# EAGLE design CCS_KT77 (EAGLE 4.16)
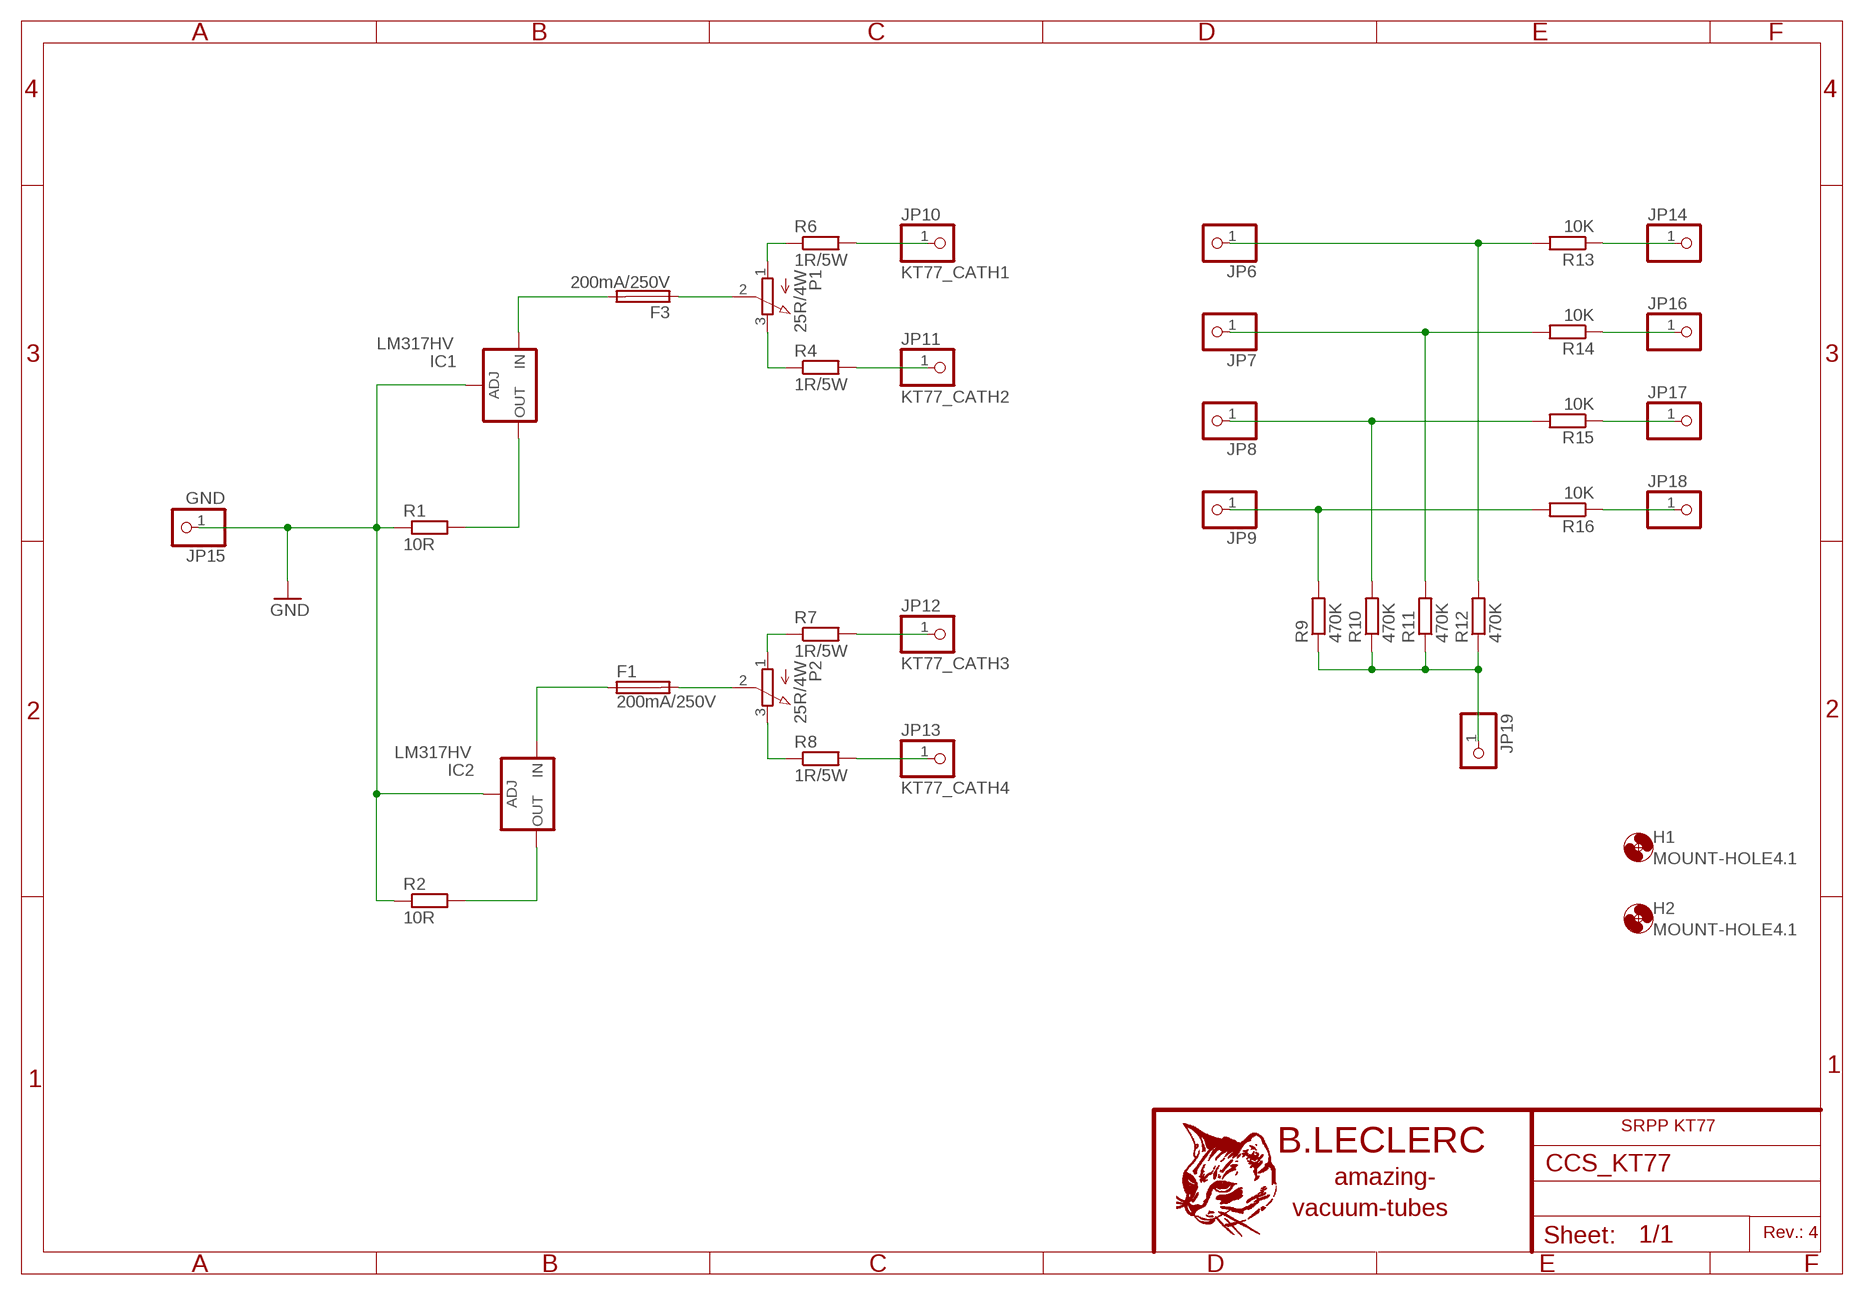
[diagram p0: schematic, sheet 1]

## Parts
F1  200mA/250V  FUSESH22  [SH22]
F3  200mA/250V  FUSESH22  [SH22]
H1  MOUNT-HOLE4.1  [4,1]
H2  MOUNT-HOLE4.1  [4,1]
IC1  LM317HV  LM317MBT  [TO220L1]
IC2  LM317HV  LM317MBT  [TO220L1]
JP6  PINHD-1X1  [1X01]
JP7  PINHD-1X1  [1X01]
JP8  PINHD-1X1  [1X01]
JP9  PINHD-1X1  [1X01]
JP10  KT77_CATH1  PINHD-1X1  [1X01]
JP11  KT77_CATH2  PINHD-1X1  [1X01]
JP12  KT77_CATH3  PINHD-1X1  [1X01]
JP13  KT77_CATH4  PINHD-1X1  [1X01]
JP14  PINHD-1X1  [1X01]
JP15  GND  PINHD-1X1  [1X01]
JP16  PINHD-1X1  [1X01]
JP17  PINHD-1X1  [1X01]
JP18  PINHD-1X1  [1X01]
JP19  PINHD-1X1  [1X01]
P1  25R/4W  STD-EU  [STD-EU]
P2  25R/4W  STD-EU  [STD-EU]
R1  10R  R-EU_0411/15  [0411/15]
R2  10R  R-EU_0411/15  [0411/15]
R4  1R/5W  R-EU_0617/17  [0617/17]
R6  1R/5W  R-EU_0617/17  [0617/17]
R7  1R/5W  R-EU_0617/17  [0617/17]
R8  1R/5W  R-EU_0617/17  [0617/17]
R9  470K  R-EU_0414/15  [0414/15]
R10  470K  R-EU_0414/15  [0414/15]
R11  470K  R-EU_0414/15  [0414/15]
R12  470K  R-EU_0414/15  [0414/15]
R13  10K  R-EU_0414/15  [0414/15]
R14  10K  R-EU_0414/15  [0414/15]
R15  10K  R-EU_0414/15  [0414/15]
R16  10K  R-EU_0414/15  [0414/15]

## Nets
GND: IC1.1(ADJ) IC2.1(ADJ) JP15.1 R1.1 R2.1
N$1: F3.1 P1.2(S)
N$2: IC2.2(OUT) R2.2
N$3: F1.2 P2.2(S)
N$4: F3.2 IC1.3(IN)
N$5: JP10.1 R6.2
N$6: JP12.1 R7.2
N$13: JP11.1 R4.2
N$14: JP13.1 R8.2
N$18: P2.1(A) R7.1
N$20: P2.3(E) R8.1
N$24: P1.3(E) R4.1
N$26: P1.1(A) R6.1
N$27: IC1.2(OUT) R1.2
N$28: F1.1 IC2.3(IN)
N$36: JP6.1 R12.2 R13.2
N$37: JP7.1 R11.2 R14.2
N$38: JP8.1 R10.2 R15.2
N$39: JP9.1 R9.2 R16.2
N$40: JP14.1 R13.1
N$41: JP16.1 R14.1
N$42: JP17.1 R15.1
N$43: JP18.1 R16.1
N$44: JP19.1 R9.1 R10.1 R11.1 R12.1

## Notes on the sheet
- SRPP KT77
- Rev.: 4

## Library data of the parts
F1 F3 = fuse:FUSE: Fuse
H1 H2 = holes:MOUNT-HOLE: MOUNTING HOLE with drill center marker
IC1 IC2 = v-reg:LM317?*: 500 mA Adjustable Output Positive Voltage Regulator Source: http://www.onsemi.co.jp .. LM317M-D.PDF
JP6-JP19 = pinhead:PINHD-1X1: PIN HEADER
P1 P2 = pot:STD-EU
R1 R2 R4 R6-R16 = rcl:R-EU_: RESISTOR, European symbol

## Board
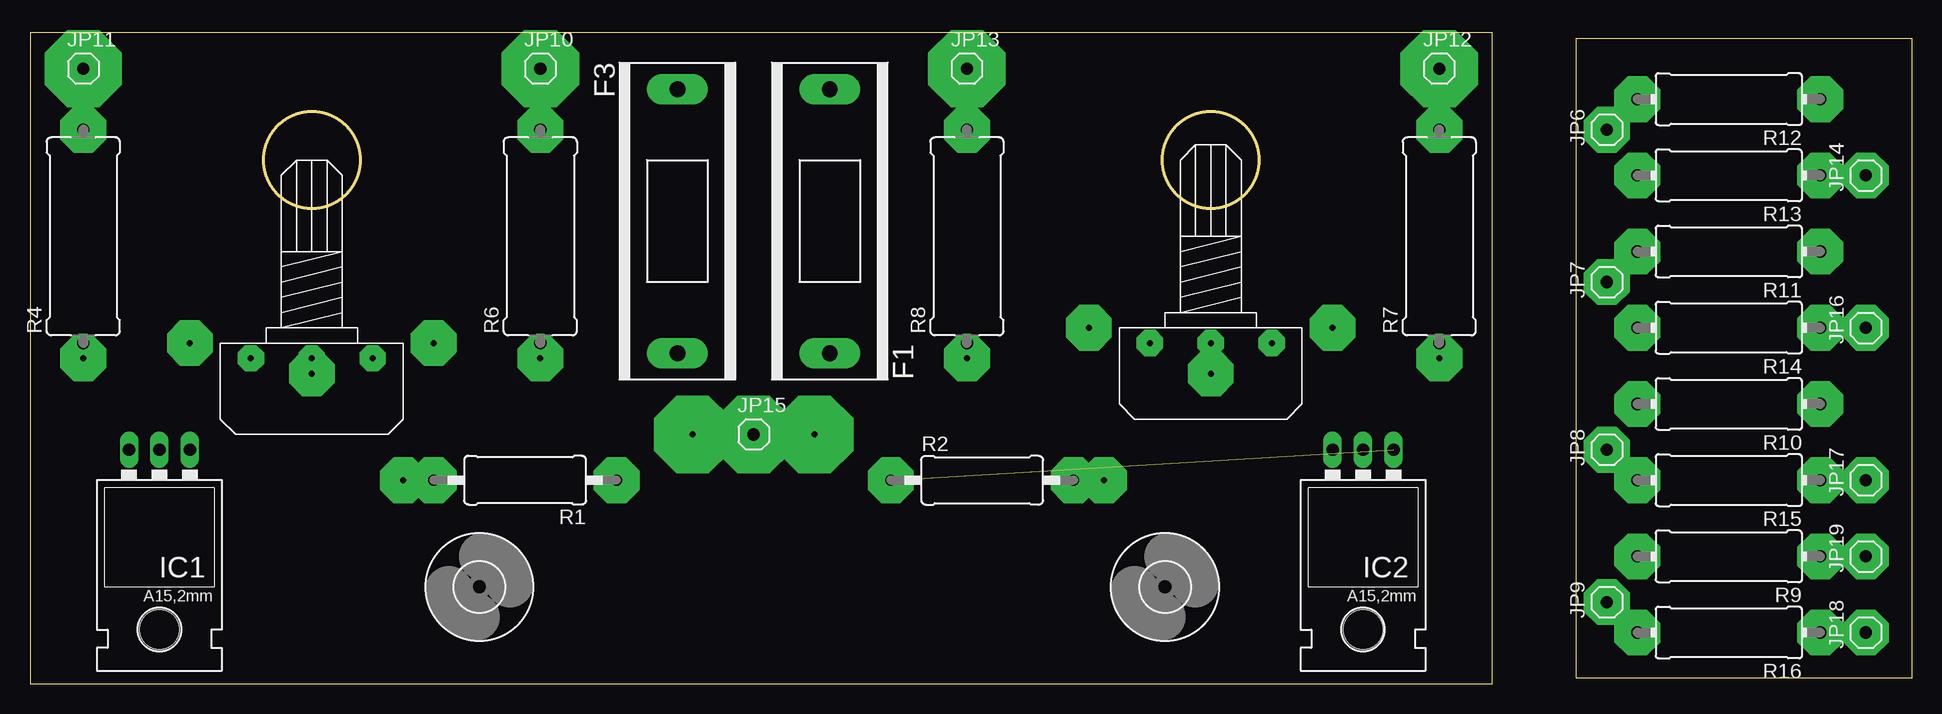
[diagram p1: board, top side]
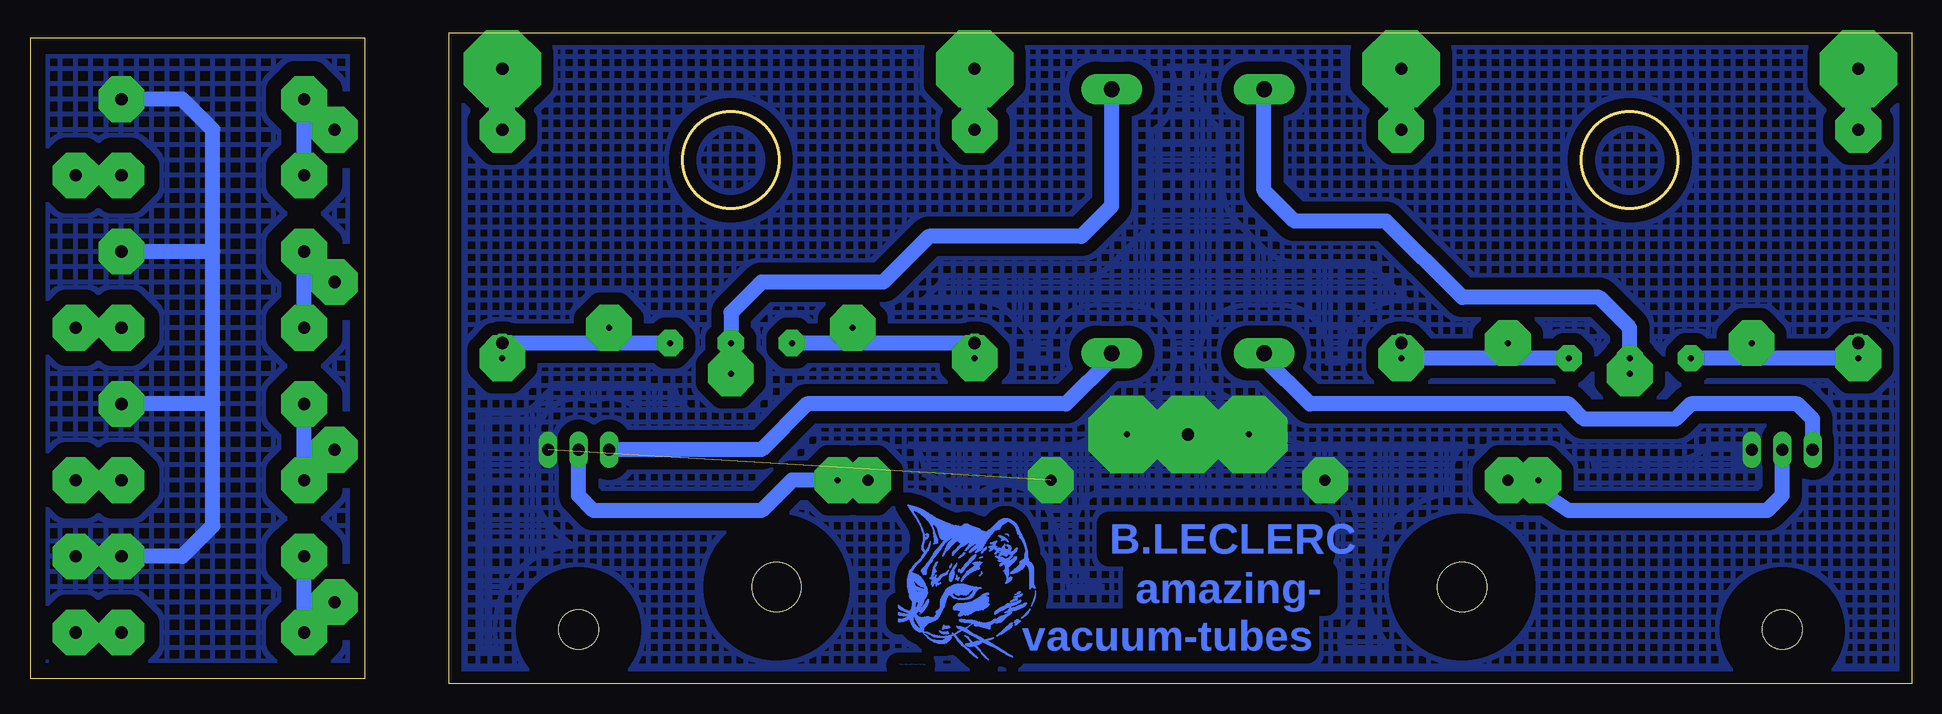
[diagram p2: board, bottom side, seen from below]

Size 156.84 x 54.28 mm. Coordinates in mm from the lower left corner, seen from the top.
Outline: 0,0 121.9,0 121.9,54.28 0,54.28 0,0
Outline: 128.9,53.81 156.84,53.81 156.84,0.47 128.9,0.47 128.9,53.81
Outline: circle at 23.49,43.65 radius 4.02
Outline: circle at 98.42,43.65 radius 4.02
Copper layers (1*16): Top 0.035mm / dielectric 1.5mm / Bottom 0.035mm
Design rules "default": minimum track width 10mil, minimum drill 24mil, track to track 8mil, track to pad 8mil, pad to pad 8mil, via to via 8mil, smd to smd 8mil, copper to edge 40mil, drill to drill 8mil, minimum pad ring 10mil, minimum via ring 8mil, stop-mask expansion 4mil, vias tented up to drill 0mil, thermal gap 10mil

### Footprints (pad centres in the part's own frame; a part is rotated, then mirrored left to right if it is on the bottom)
SH22 = drill 1.321 pad 2.54 long: 1 -10.998,0; 2 10.998,0
4,1 = hole 4.1: 0,0
TO220L1 = drill 1.016 long: 1 -2.54,-3.81; 2 0,-3.81; 3 2.54,-3.81 | hole 3.302: 0,11.176
1X01 = drill 1.016 octagon: 1 0,0
STD-EU = drill 0.5 pad 2.184 octagon: 1 -5.08,0; 2 0,0; 3 5.08,0
0411/15 = drill 0.914 octagon: 1 -7.62,0; 2 7.62,0
0617/17 = drill 1.016 octagon: 1 -8.89,0; 2 8.89,0
0414/15 = drill 1.016 octagon: 1 -7.62,0; 2 7.62,0

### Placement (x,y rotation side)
F1  66.67,38.57 90 top
F3  53.97,38.57 270 top
H1  94.61,8.09 0 top
H2  37.46,8.09 0 top
IC1  10.79,15.71 180 top
IC2  111.12,15.71 180 top
JP6  131.44,46.19 90 top
JP7  131.44,33.49 90 top
JP8  131.44,19.52 90 top
JP9  131.44,6.82 90 top
JP10  42.54,51.27 0 top
JP11  4.44,51.27 0 top
JP12  117.47,51.27 0 top
JP13  78.1,51.27 0 top
JP14  153.03,42.38 90 top
JP15  60.32,20.79 0 top
JP16  153.03,29.68 90 top
JP17  153.03,16.98 90 top
JP18  153.03,4.28 90 top
JP19  153.03,10.63 90 top
P1  23.49,27.14 180 top
P2  98.42,28.41 180 top
R1  41.27,16.98 180 top
R2  79.37,16.98 0 top
R4  4.44,37.3 90 top
R6  42.54,37.3 90 top
R7  117.47,37.3 90 top
R8  78.1,37.3 90 top
R9  141.6,10.63 180 top
R10  141.6,23.33 180 top
R11  141.6,36.03 180 top
R12  141.6,48.73 180 top
R13  141.6,42.38 180 top
R14  141.6,29.68 180 top
R15  141.6,16.98 180 top
R16  141.6,4.28 180 top
U$2  [CHAT1]  84.45,1.74 0 bottom

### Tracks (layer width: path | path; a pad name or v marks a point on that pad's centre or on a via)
GND  (via drill 0.5 pad 1.27, 0.5 pad 3.81, 0.5 pad 6.45)  (1 unrouted)
  other vias: 60.32,20.79 65.4,20.79 60.32,20.79 55.24,20.79 48.89,16.98 71.75,16.98 13.33,19.52 113.66,19.52
  pour Bottom (isolate 2.54, no thermals, hatched): 0.63,53.81 121.28,53.81 121.28,0.47 0.63,0.47
  pour Bottom (isolate 1.016, no thermals, hatched): 0.63,53.81 121.28,53.81 121.28,0.47 0.63,0.47
N$1
  Bottom 1.27: F3.1 53.97,41.11 51.43,38.57 43.81,38.57 37.46,32.22 26.03,32.22 23.49,29.68 P1.2
N$2
  Bottom 1.27: R2.2 93.34,16.98 95.88,14.44 109.85,14.44 111.12,15.71 IC2.2
N$3
  Bottom 1.27: F1.2 66.67,39.84 69.21,37.3 81.91,37.3 85.72,33.49 95.88,33.49 98.42,30.95 P2.2
N$4
  Bottom 1.27: IC1.3 8.25,22.06 9.52,23.33 18.41,23.33 19.68,22.06 27.3,22.06 28.57,23.33 50.16,23.33 53.97,27.14 F3.2
N$5
  Bottom 2.184: R6.2 JP10.1
N$6
  Bottom 2.184: R7.2 JP12.1
N$7  (via drill 0.5 pad 6.45)
  other vias: 117.47,51.27
N$8  (via drill 0.5 pad 6.45)
  other vias: 78.1,51.27
N$9  (via drill 0.5 pad 6.45)
  other vias: 42.54,51.27
N$10  (via drill 0.5 pad 6.45)
  other vias: 4.44,51.27
N$11  (via drill 0.5 pad 3.81)
  other vias: 88.26,29.68
N$12  (via drill 0.5 pad 3.81)
  other vias: 42.54,27.14
N$13
  Bottom 2.184: R4.2 JP11.1
N$14
  Bottom 2.184: R8.2 JP13.1
N$15  (via drill 0.5 pad 3.81)
  other vias: 78.1,27.14
N$16  (via drill 0.5 pad 3.81)
  other vias: 42.54,46.19
N$17  (via drill 0.5 pad 3.81)
  other vias: 78.1,46.19
N$18
  Bottom 1.27: P2.1 R7.1
N$19  (via drill 0.5 pad 3.81)
  other vias: 117.47,27.14
N$20
  Bottom 1.27: R8.1 P2.3
N$21  (via drill 0.5 pad 3.81)
  other vias: 4.44,27.14
N$22  (via drill 0.5 pad 3.81)
  other vias: 4.44,46.19
N$23  (via drill 0.5 pad 3.81)
  other vias: 117.47,46.19
N$24
  Bottom 1.27: P1.3 4.44,27.14 R4.1
N$25  (via drill 0.5 pad 3.81)
  other vias: 108.58,29.68
N$26
  Bottom 1.27: P1.1 42.54,27.14 R6.1
N$27
  Bottom 1.27: R1.2 32.38,16.98 28.57,14.44 12.06,14.44 10.79,15.71 IC1.2
N$28
  Bottom 1.27: F1.1 66.67,27.14 70.48,23.33 92.07,23.33 95.88,19.52 IC2.3
N$29  (via drill 0.5 pad 3.81)
  other vias: 31.11,16.98
N$30  (via drill 0.5 pad 3.81)
  other vias: 89.53,16.98
N$31  (via drill 0.5 pad 3.81)
  other vias: 33.65,16.98
N$32  (via drill 0.5 pad 3.81)
  other vias: 23.49,25.87
N$33  (via drill 0.5 pad 3.81)
  other vias: 33.65,28.41
N$34  (via drill 0.5 pad 3.81)
  other vias: 13.33,28.41
N$35  (via drill 0.5 pad 3.81)
  other vias: 98.42,25.87
N$36
  Bottom 1.27: R13.2 133.98,46.19 | 133.98,46.19 R12.2 | 133.98,46.19 JP6.1
N$37
  Bottom 1.27: R14.2 133.98,33.49 | 133.98,33.49 R11.2 | 133.98,33.49 JP7.1
N$38
  Bottom 1.27: R15.2 133.98,19.52 | 133.98,19.52 R10.2 | 133.98,19.52 JP8.1
N$39
  Bottom 1.27: R16.2 133.98,6.82 | 133.98,6.82 R9.2 | 133.98,6.82 JP9.1
N$40
  Bottom 1.27: R13.1 JP14.1
N$41
  Bottom 1.27: R14.1 JP16.1
N$42
  Bottom 1.27: R15.1 JP17.1
N$43
  Bottom 1.27: R16.1 JP18.1
N$44  (via drill 0.5 pad 3.81)
  Bottom 1.27: R12.1 144.14,48.73 141.6,46.19 141.6,36.03 | 141.6,23.33 141.6,13.17 144.14,10.63 R9.1 JP19.1 | 141.6,23.33 141.6,36.03 | 141.6,36.03 R11.1 | 141.6,23.33 R10.1
  other vias: 153.03,10.63 149.22,10.63 149.22,23.33 149.22,36.03 149.22,48.73
  pour Bottom (isolate 1.27, no thermals, hatched): 130.17,52.54 155.57,52.54 155.57,1.74 130.17,1.74
N$45  (via drill 0.5 pad 3.81)
  other vias: 133.98,36.03
N$46  (via drill 0.5 pad 3.81)
  other vias: 133.98,42.38
N$47  (via drill 0.5 pad 3.81)
  other vias: 86.99,16.98
N$48  (via drill 0.5 pad 3.81)
  other vias: 153.03,42.38
N$49  (via drill 0.5 pad 3.81)
  other vias: 149.22,42.38
N$50  (via drill 0.5 pad 1.27)
  other vias: 8.25,19.52
N$51  (via drill 0.5 pad 3.81)
  other vias: 131.44,46.19
N$52  (via drill 0.5 pad 3.81)
  other vias: 131.44,33.49
N$53  (via drill 0.5 pad 3.81)
  other vias: 133.98,48.73
N$54  (via drill 0.5 pad 3.81)
  other vias: 133.98,29.68
N$55  (via drill 0.5 pad 3.81)
  other vias: 149.22,29.68
N$56  (via drill 0.5 pad 3.81)
  other vias: 153.03,29.68
N$57  (via drill 0.5 pad 1.27)
  other vias: 10.79,19.52
N$58  (via drill 0.5 pad 3.81)
  other vias: 133.98,23.33
N$59  (via drill 0.5 pad 3.81)
  other vias: 131.44,19.52
N$60  (via drill 0.5 pad 3.81)
  other vias: 133.98,16.98
N$61  (via drill 0.5 pad 3.81)
  other vias: 149.22,16.98
N$62  (via drill 0.5 pad 3.81)
  other vias: 153.03,16.98
N$64  (via drill 0.5 pad 1.27)
  other vias: 108.58,19.52
N$65  (via drill 0.5 pad 3.81)
  other vias: 133.98,10.63
N$66  (via drill 0.5 pad 3.81)
  other vias: 131.44,6.82
N$67  (via drill 0.5 pad 3.81)
  other vias: 133.98,4.28
N$68  (via drill 0.5 pad 3.81)
  other vias: 149.22,4.28
N$69  (via drill 0.5 pad 3.81)
  other vias: 153.03,4.28
N$70  (via drill 0.5 pad 1.27)
  other vias: 111.12,19.52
